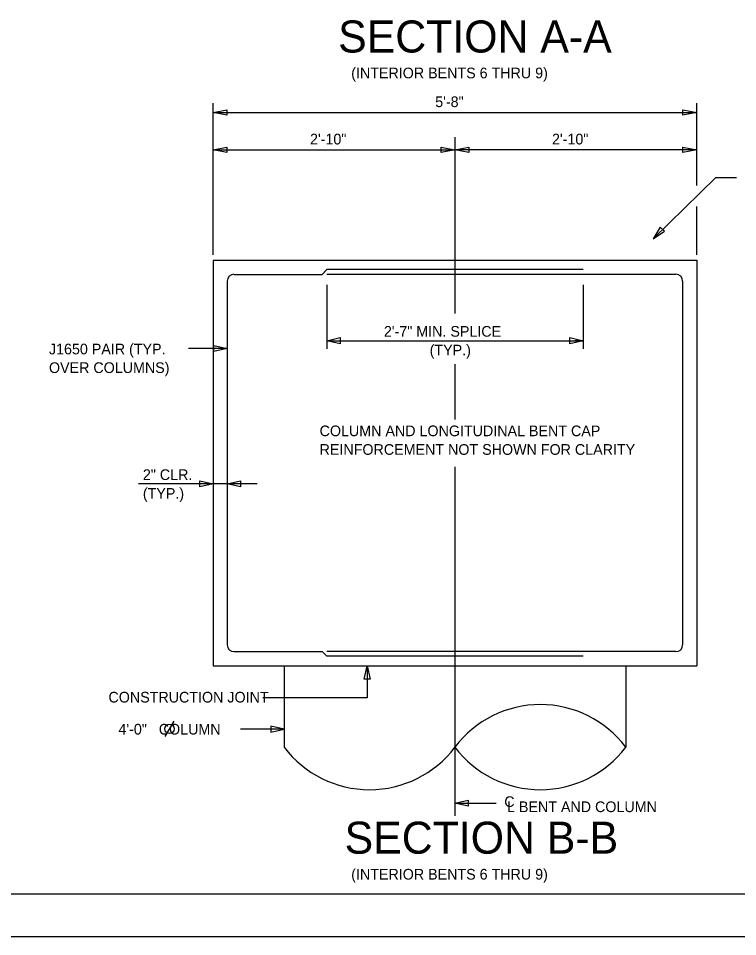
# Model space of a CAD drawing. Extents: x -133.1 to -97, y -1.7 to 20.3.
# Drawn here: x -118.94 to -110.52, y -1.69 to 9.06 of the extents above; entities that cross this region are included whole.
import ezdxf

# ---------------------------------------------------------------- set-up
doc = ezdxf.new("R2010")
doc.units = 0
for name, color, linetype in [('BR_AUTO DIMENSION', 7, 'Continuous'), ('BR_BORDER LINES', 7, 'Continuous'), ('BR_CENTER LINES', 7, 'Continuous'), ('BR_CONCRETE', 7, 'Continuous'), ('BR_REBAR', 7, 'Continuous'), ('BR_TEXT', 7, 'Continuous'), ('Level 31', 7, 'Continuous')]:
    doc.layers.add(name, color=color, linetype=linetype)

msp = doc.modelspace()

# ---------------------------------------------------------------- linework, layer by layer
at = {"layer": 'BR_AUTO DIMENSION'}
for p, q in [((-116.664, 6.292), (-116.664, 8.066)), ((-110.997, 7.102), (-110.997, 8.066)), ((-116.664, 7.959), (-110.997, 7.959)), ((-116.664, 7.522), (-113.831, 7.522)), ((-110.997, 7.522), (-113.831, 7.522)), ((-110.997, 6.292), (-110.997, 6.857)), ((-115.331, 5.942), (-115.331, 5.189)), ((-112.331, 5.942), (-112.331, 5.189)), ((-115.331, 5.286), (-112.331, 5.286)), ((-116.497, 5.195), (-116.951, 5.195)), ((-116.146, 3.611), (-117.538, 3.611)), ((-114.858, 1.479), (-114.858, 1.106)), ((-114.858, 1.106), (-116.082, 1.106)), ((-115.831, 0.738), (-116.343, 0.738)), ((-113.831, -0.128), (-113.348, -0.128))]:
    msp.add_line(p, q, dxfattribs=at)
for points in [[(-116.502, 7.927), (-116.664, 7.959), (-116.502, 7.99)], [(-111.16, 7.99), (-110.997, 7.959), (-111.16, 7.927)], [(-116.502, 7.491), (-116.664, 7.522), (-116.502, 7.553)], [(-113.993, 7.553), (-113.831, 7.522), (-113.993, 7.491)], [(-113.668, 7.491), (-113.831, 7.522), (-113.668, 7.553)], [(-111.16, 7.553), (-110.997, 7.522), (-111.16, 7.491)], [(-111.429, 6.616), (-111.511, 6.479), (-111.377, 6.567)], [(-115.175, 5.25), (-115.331, 5.286), (-115.175, 5.322)], [(-112.487, 5.322), (-112.331, 5.286), (-112.487, 5.25)], [(-116.653, 5.231), (-116.497, 5.195), (-116.653, 5.159)], [(-116.82, 3.647), (-116.664, 3.611), (-116.82, 3.575)], [(-116.342, 3.575), (-116.497, 3.611), (-116.342, 3.647)], [(-114.894, 1.323), (-114.858, 1.479), (-114.822, 1.323)], [(-115.987, 0.702), (-115.831, 0.738), (-115.987, 0.774)], [(-113.675, -0.164), (-113.831, -0.128), (-113.675, -0.092)]]:
    msp.add_lwpolyline(points, close=True, dxfattribs=at)
msp.add_lwpolyline([(-111.511, 6.479), (-110.777, 7.195), (-110.533, 7.195)], dxfattribs=at)
at = {"layer": 'BR_BORDER LINES'}
msp.add_line((-131.308, -1.191), (-97.642, -1.191), dxfattribs=at)
at = {"layer": 'BR_CENTER LINES'}
for p, q in [((-113.831, 7.669), (-113.831, 5.605)), ((-113.831, 5.011), (-113.831, 4.363)), ((-113.831, 3.808), (-113.831, -0.278))]:
    msp.add_line(p, q, dxfattribs=at)
at = {"layer": 'BR_CONCRETE'}
for p, q in [((-116.664, 6.229), (-116.664, 1.479)), ((-116.664, 6.229), (-110.997, 6.229)), ((-110.997, 6.229), (-110.997, 1.479)), ((-116.664, 1.479), (-115.831, 1.479)), ((-115.831, 1.479), (-111.831, 1.479)), ((-115.831, 1.479), (-115.831, 0.528)), ((-111.831, 1.479), (-110.997, 1.479)), ((-111.831, 1.479), (-111.831, 0.528))]:
    msp.add_line(p, q, dxfattribs=at)
for centre, start, end in [((-112.831, -0.226), 37.0023, 142.9977), ((-114.831, 1.281), 217.0023, 322.9977), ((-112.831, 1.281), 217.0023, 322.9977)]:
    msp.add_arc(centre, 1.252, start, end, dxfattribs=at)
at = {"layer": 'BR_REBAR'}
for p, q in [((-116.419, 6.063), (-115.386, 6.063)), ((-115.386, 6.063), (-115.331, 6.118)), ((-112.331, 6.118), (-115.331, 6.118)), ((-111.242, 6.063), (-115.331, 6.063)), ((-116.497, 5.985), (-116.497, 1.724)), ((-111.164, 5.985), (-111.164, 1.724)), ((-116.419, 1.646), (-115.386, 1.646)), ((-115.386, 1.646), (-115.331, 1.591)), ((-111.242, 1.646), (-115.331, 1.646)), ((-112.331, 1.591), (-115.331, 1.591))]:
    msp.add_line(p, q, dxfattribs=at)
for centre, start, end in [((-116.419, 5.985), 90, 180), ((-111.242, 5.985), 360, 90), ((-116.419, 1.724), 180, 270), ((-111.242, 1.724), 270, 360)]:
    msp.add_arc(centre, 0.0781, start, end, dxfattribs=at)
at = {"layer": 'BR_TEXT'}
for p, q in [((-115.331, 5.286), (-115.253, 5.286)), ((-112.331, 5.286), (-112.428, 5.286)), ((-117.225, 0.651), (-117.12, 0.832))]:
    msp.add_line(p, q, dxfattribs=at)
msp.add_circle((-117.173, 0.741), 0.055, dxfattribs=at)
at = {"layer": 'Level 31'}
msp.add_lwpolyline([(-133.141, -1.691), (-97.141, -1.691), (-97.141, 20.309), (-133.141, 20.309)], close=True, dxfattribs=at)

# ---------------------------------------------------------------- texts
at = {"layer": 'BR_AUTO DIMENSION'}
for s, p in [('5\'-8"', (-114.062, 8.021)), ('2\'-10"', (-115.528, 7.584)), ('2\'-10"', (-112.694, 7.584))]:
    msp.add_text(s, height=0.125, dxfattribs=at).set_placement(p)
at = {"layer": 'BR_TEXT'}
for s, p in [('SECTION A-A', (-115.199, 8.66)), ('SECTION B-B', (-115.123, -0.72))]:
    msp.add_text(s, height=0.375, dxfattribs=at).set_placement(p)
for s, p in [('(INTERIOR BENTS 6 THRU 9)', (-115.046, 8.358)), ('2\'-7" MIN. SPLICE', (-114.663, 5.333)), ('J1650 PAIR (TYP.', (-118.586, 5.126)), ('(TYP.)', (-114.127, 5.114)), ('OVER COLUMNS)', (-118.586, 4.908)), ('COLUMN AND LONGITUDINAL BENT CAP', (-115.416, 4.168)), ('REINFORCEMENT NOT SHOWN FOR CLARITY', (-115.416, 3.95)), ('2" CLR.', (-117.486, 3.655)), ('(TYP.)', (-117.486, 3.436)), ('CONSTRUCTION JOINT', (-117.889, 1.05)), ('4\'-0"   COLUMN', (-117.772, 0.675)), ('C', (-113.253, -0.173)), ('L BENT AND COLUMN', (-113.221, -0.233)), ('(INTERIOR BENTS 6 THRU 9)', (-115.046, -1.023))]:
    msp.add_text(s, height=0.125, rotation=360, dxfattribs=at).set_placement(p)

doc.saveas('drawing.dxf')
